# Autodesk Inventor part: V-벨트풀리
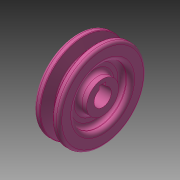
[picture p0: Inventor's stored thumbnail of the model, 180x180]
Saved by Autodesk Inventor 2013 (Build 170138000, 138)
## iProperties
Created: 2015-12
Part Number: V-벨트풀리
Material: 강철, 연강
Document SubType Name: Modeling
Designer: mduedu
Density: 7.86 g/cm^3
Author: mduedu
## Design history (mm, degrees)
sketch "스케치1"
  geometry: L1 (-9.5, 0)-(9.5, 0); L2 (-9.5, 0)-(-9.5, 32.7); L3 (-9.5, 32.7)-(-4.825, 32.7); L4 (-4.825, 32.7)-(-2.074, 23.7); L5 (-2.074, 23.7)-(0, 23.7); L6 (0, 0)-(0, 23.7); L7 (9.5, 0)-(9.5, 32.7); L8 (9.5, 32.7)-(4.825, 32.7); L9 (4.825, 32.7)-(2.074, 23.7); L10 (2.074, 23.7)-(0, 23.7); L11 (-4, 30)-(4, 30); 3 further points
  constraints: 22 end point, 3 coincident, 3 perpendicular, 3 symmetric about line, 2 parallel, 2 point on line, 1 horizontal, 1 midpoint, 1 vertical alignment
  dimensions: "d0" = 19 distance between parallel lines of L7 L2; "d2" = 6.3 distance between parallel lines of L10 L11; "d3" = 34 deg angle of L9 L4; "d4" = 2.7 distance between parallel lines of L11 L8; "d5" = 60 diameter of L11 L1; "d6" = 8 distance of L11.end L11.start
revolve "회전1" sketch "스케치1" stored, may be unused: angle "d7" = 90 deg
sketch "스케치2"
  geometry: C1 r 21 at (0, 0); C2 r 12 at (0, 0); 1 further point
  constraints: 2 centre point, 2 coincident
  dimensions: "d8" = 42 diameter of C1; "d10" = 24 diameter of C2
extrude "돌출1" cut sketch "스케치2" distance "d11" = 6.5; taper "d12" = 0 deg
fillet "모깎기1" dims "d13" = 1, "d14" = 0.5, "d15" = 2
fillet "모깎기2" dims "d16" = 3
fillet "모깎기3" dims "d17" = 3
hole "구멍1" diameter "d20" = 13; stored, may be unused: countersink angle "d24" = 90 deg, drill point angle "d26" = 118 deg; dims "d18" = 10, "d19" = 10, "d21" = 6, "d22" = 4, "d23" = 2, "d25" = 8
sketch "스케치3"
  geometry: L1 (-2.5, 0)-(2.5, 0); L2 (2.5, 0)-(2.5, 8.8); L3 (2.5, 8.8)-(-2.5, 8.8); L4 (-2.5, 8.8)-(-2.5, 0); 2 further points
  constraints: 8 end point, 2 parallel, 1 coincident, 1 horizontal, 1 midpoint, 1 perpendicular
  dimensions: "d27" = 8.8 distance of L1.end L2.end; "d29" = 5 distance of L2.end L3.end
extrude "돌출2" cut sketch "스케치3" stored distance "d30" = 6.5; taper "d31" = 0 deg
node "솔리드1"
mirror "대칭1"
